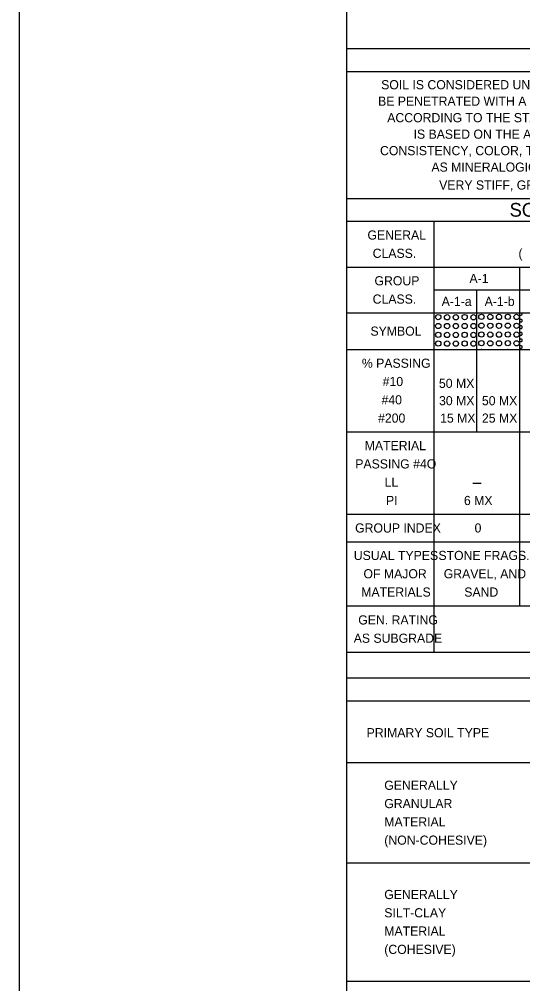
# Model space of a CAD drawing. Extents: x 278618 to 280654, y 171155 to 171855.
# Drawn here: x 280458.63 to 280482.47, y 171577.39 to 171623.09 of the extents above; entities that cross this region are included whole.
import ezdxf

# ---------------------------------------------------------------- set-up
doc = ezdxf.new("R2010")
doc.units = 0
doc.layers.add('Geotech Sheets and Borders Cell', color=7, linetype='Continuous')
doc.layers.add('Sheet Plot Border Inside CELL', color=7, linetype='Continuous')

msp = doc.modelspace()

# ---------------------------------------------------------------- linework, layer by layer
at = {"layer": 'Geotech Sheets and Borders Cell'}
for p, q in [((280474.148, 171621.702), (280624.148, 171621.702)), ((280474.148, 171620.618), (280624.148, 171620.618)), ((280474.148, 171614.6), (280511.888, 171614.6)), ((280474.148, 171613.515), (280511.888, 171613.515)), ((280478.269, 171613.515), (280478.269, 171593.093)), ((280474.148, 171611.346), (280511.888, 171611.346)), ((280482.338, 171595.296), (280482.338, 171611.346)), ((280478.269, 171610.262), (280500.609, 171610.262)), ((280480.308, 171603.538), (280480.308, 171610.262)), ((280474.148, 171609.177), (280511.888, 171609.177)), ((280479.515, 171609.176), (280479.514, 171609.177)), ((280479.515, 171609.176), (280479.515, 171609.176)), ((280480.308, 171607.94), (280480.308, 171607.94)), ((280474.148, 171607.442), (280511.888, 171607.442)), ((280474.148, 171603.538), (280511.888, 171603.538)), ((280480.104, 171601.11), (280480.503, 171601.11)), ((280474.148, 171599.634), (280500.609, 171599.634)), ((280474.148, 171598.333), (280500.609, 171598.333)), ((280474.148, 171595.296), (280511.888, 171595.296)), ((280474.148, 171593.093), (280511.888, 171593.093)), ((280549.148, 171591.865), (280474.148, 171591.865)), ((280549.148, 171590.781), (280474.148, 171590.781)), ((280474.148, 171587.864), (280511.888, 171587.864)), ((280474.148, 171583.122), (280511.888, 171583.122)), ((280474.148, 171577.514), (280549.148, 171577.514))]:
    msp.add_line(p, q, dxfattribs=at)
msp.add_lwpolyline([(280474.148, 171646.488), (280624.148, 171646.488), (280624.148, 171541.488), (280474.148, 171541.488)], close=True, dxfattribs=at)
for centre in [(280478.473, 171608.974), (280478.892, 171608.968), (280479.306, 171608.968), (280479.723, 171608.974), (280480.142, 171608.968), (280480.516, 171608.989), (280480.935, 171608.982), (280481.349, 171608.982), (280481.766, 171608.989), (280482.185, 171608.982), (280478.473, 171608.554), (280478.892, 171608.549), (280479.306, 171608.549), (280479.723, 171608.554), (280480.142, 171608.549), (280480.516, 171608.569), (280480.935, 171608.564), (280481.349, 171608.564), (280481.766, 171608.569), (280482.185, 171608.564), (280478.473, 171608.135), (280478.473, 171607.724), (280478.892, 171608.13), (280478.892, 171607.718), (280479.306, 171608.13), (280479.306, 171607.718), (280479.723, 171608.135), (280479.723, 171607.724), (280480.142, 171608.13), (280480.142, 171607.718), (280480.516, 171608.15), (280480.516, 171607.739), (280480.935, 171608.145), (280480.935, 171607.732), (280481.349, 171608.145), (280481.349, 171607.732), (280481.766, 171608.15), (280481.766, 171607.739), (280482.185, 171608.145), (280482.185, 171607.732)]:
    msp.add_circle(centre, 0.125, dxfattribs=at)
for centre, radius, start, end in [((280482.391, 171609.122), 0.0625, 117.2937, 147.8104), ((280482.391, 171609.122), 0.0625, 212.1896, 62.7063), ((280482.391, 171608.809), 0.0625, 212.1896, 147.8104), ((280482.391, 171608.497), 0.0625, 212.1896, 147.8104), ((280482.391, 171608.184), 0.0625, 212.1896, 147.8104), ((280482.391, 171607.872), 0.0625, 212.1896, 147.8104), ((280480.516, 171607.319), 0.125, 82.1331, 97.8669), ((280481.766, 171607.319), 0.125, 82.1331, 97.8669), ((280482.391, 171607.559), 0.0625, 212.1896, 147.8104)]:
    msp.add_arc(centre, radius, start, end, dxfattribs=at)
at = {"layer": 'Sheet Plot Border Inside CELL'}
msp.add_lwpolyline([(280458.631, 171541.204), (280625.398, 171541.204), (280625.398, 171646.771), (280458.631, 171646.771)], close=True, dxfattribs=at)

# ---------------------------------------------------------------- texts
at = {"layer": 'Geotech Sheets and Borders Cell'}
for s, height, p in [('SOIL IS CONSIDERED UNCONSOLIDATED, SEMI-CONSOLIDATED, OR WEATHERED EARTH MATERIALS THAT CAN', 0.43381, (280475.768, 171619.769)), ('BE PENETRATED WITH A CONTINUOUS FLIGHT POWER AUGER AND YIELD LESS THAN 100 BLOWS PER FOOT', 0.43381, (280475.622, 171618.988)), ('ACCORDING TO THE STANDARD PENETRATION TEST (AASHTO T 206, ASTM D1586).  SOIL CLASSIFICATION', 0.43381, (280476.057, 171618.207)), ('IS BASED ON THE AASHTO SYSTEM.  BASIC DESCRIPTIONS GENERALLY INCLUDE THE FOLLOWING:', 0.43381, (280477.304, 171617.426)), ('CONSISTENCY, COLOR, TEXTURE, MOISTURE, AASHTO CLASSIFICATION, AND OTHER PERTINENT FACTORS SUCH ', 0.43381, (280475.716, 171616.646)), ('AS MINERALOGICAL COMPOSITION, ANGULARITY, STRUCTURE, PLASTICITY, ETC.  FOR EXAMPLE,', 0.43381, (280478.149, 171615.865)), ('VERY STIFF, GRAY, SILTY CLAY, MOIST WITH INTERBEDDED FINE SAND LAYERS, HIGHLY PLASTIC, A-7-6', 0.43381, (280478.516, 171615.016)), ('SOIL LEGEND AND AASHTO CLASSIFICATION', 0.6507, (280481.852, 171613.733)), ('GENERAL', 0.4338, (280475.121, 171612.647)), ('CLASS.', 0.4338, (280475.367, 171611.781)), ('(     35% PASSING #200)', 0.43381, (280482.273, 171611.781)), ('A-1', 0.4338, (280479.951, 171610.587)), ('GROUP', 0.4338, (280475.454, 171610.478)), ('CLASS.', 0.4338, (280475.367, 171609.612)), ('A-1-a', 0.4338, (280478.635, 171609.503)), ('A-1-b', 0.4338, (280480.67, 171609.503)), ('SYMBOL', 0.4338, (280475.263, 171608.093)), ('% PASSING', 0.4338, (280474.855, 171606.574)), ('#10', 0.4338, (280475.842, 171605.707)), ('50 MX', 0.4338, (280478.506, 171605.62)), ('#40', 0.4338, (280475.787, 171604.84)), ('30 MX', 0.4338, (280478.511, 171604.797)), ('50 MX', 0.4338, (280480.541, 171604.797)), ('#200', 0.4338, (280475.623, 171603.973)), ('15 MX', 0.4338, (280478.561, 171603.973)), ('25 MX', 0.4338, (280480.541, 171603.973)), ('MATERIAL', 0.4338, (280474.99, 171602.67)), ('PASSING #4O', 0.43381, (280474.543, 171601.803)), ('LL', 0.4338, (280475.936, 171600.936)), ('PI', 0.4338, (280475.998, 171600.069)), ('6 MX', 0.4338, (280479.69, 171600.069)), ('GROUP INDEX', 0.43381, (280474.535, 171598.767)), ('0', 0.434, (280480.194, 171598.767)), ('USUAL TYPES', 0.43381, (280474.471, 171597.465)), ('STONE FRAGS.', 0.43381, (280478.481, 171597.465)), ('OF MAJOR', 0.4338, (280474.932, 171596.598)), ('GRAVEL, AND', 0.43381, (280478.732, 171596.598)), ('MATERIALS', 0.4338, (280474.827, 171595.731)), ('SAND', 0.4338, (280479.705, 171595.731)), ('GEN. RATING', 0.43381, (280474.685, 171594.411)), ('AS SUBGRADE', 0.43381, (280474.469, 171593.544)), ('PRIMARY SOIL TYPE', 0.43381, (280475.082, 171589.066)), ('GENERALLY', 0.4338, (280475.917, 171586.577)), ('GRANULAR', 0.4338, (280475.917, 171585.71)), ('MATERIAL', 0.4338, (280475.917, 171584.843)), ('(NON-COHESIVE)', 0.43381, (280475.917, 171583.976)), ('GENERALLY', 0.4338, (280475.917, 171581.401)), ('SILT-CLAY', 0.4338, (280475.917, 171580.534)), ('MATERIAL', 0.4338, (280475.917, 171579.668)), ('(COHESIVE)', 0.4338, (280475.917, 171578.801))]:
    msp.add_text(s, height=height, dxfattribs=at).set_placement(p)

doc.saveas('drawing.dxf')
